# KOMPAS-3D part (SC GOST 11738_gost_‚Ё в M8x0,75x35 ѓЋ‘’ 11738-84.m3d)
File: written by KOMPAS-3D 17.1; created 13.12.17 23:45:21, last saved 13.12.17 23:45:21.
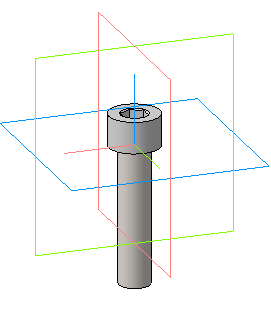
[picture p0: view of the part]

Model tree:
1. Операция без истории:1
